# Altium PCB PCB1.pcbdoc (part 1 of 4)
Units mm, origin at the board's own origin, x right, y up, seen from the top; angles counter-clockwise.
Board outline 94.87 x 122.94 mm, 4 copper layers (Top Layer, Inner1, Inner2, Bottom Layer); 129 components, 127 nets, 713 pads, 345 vias.
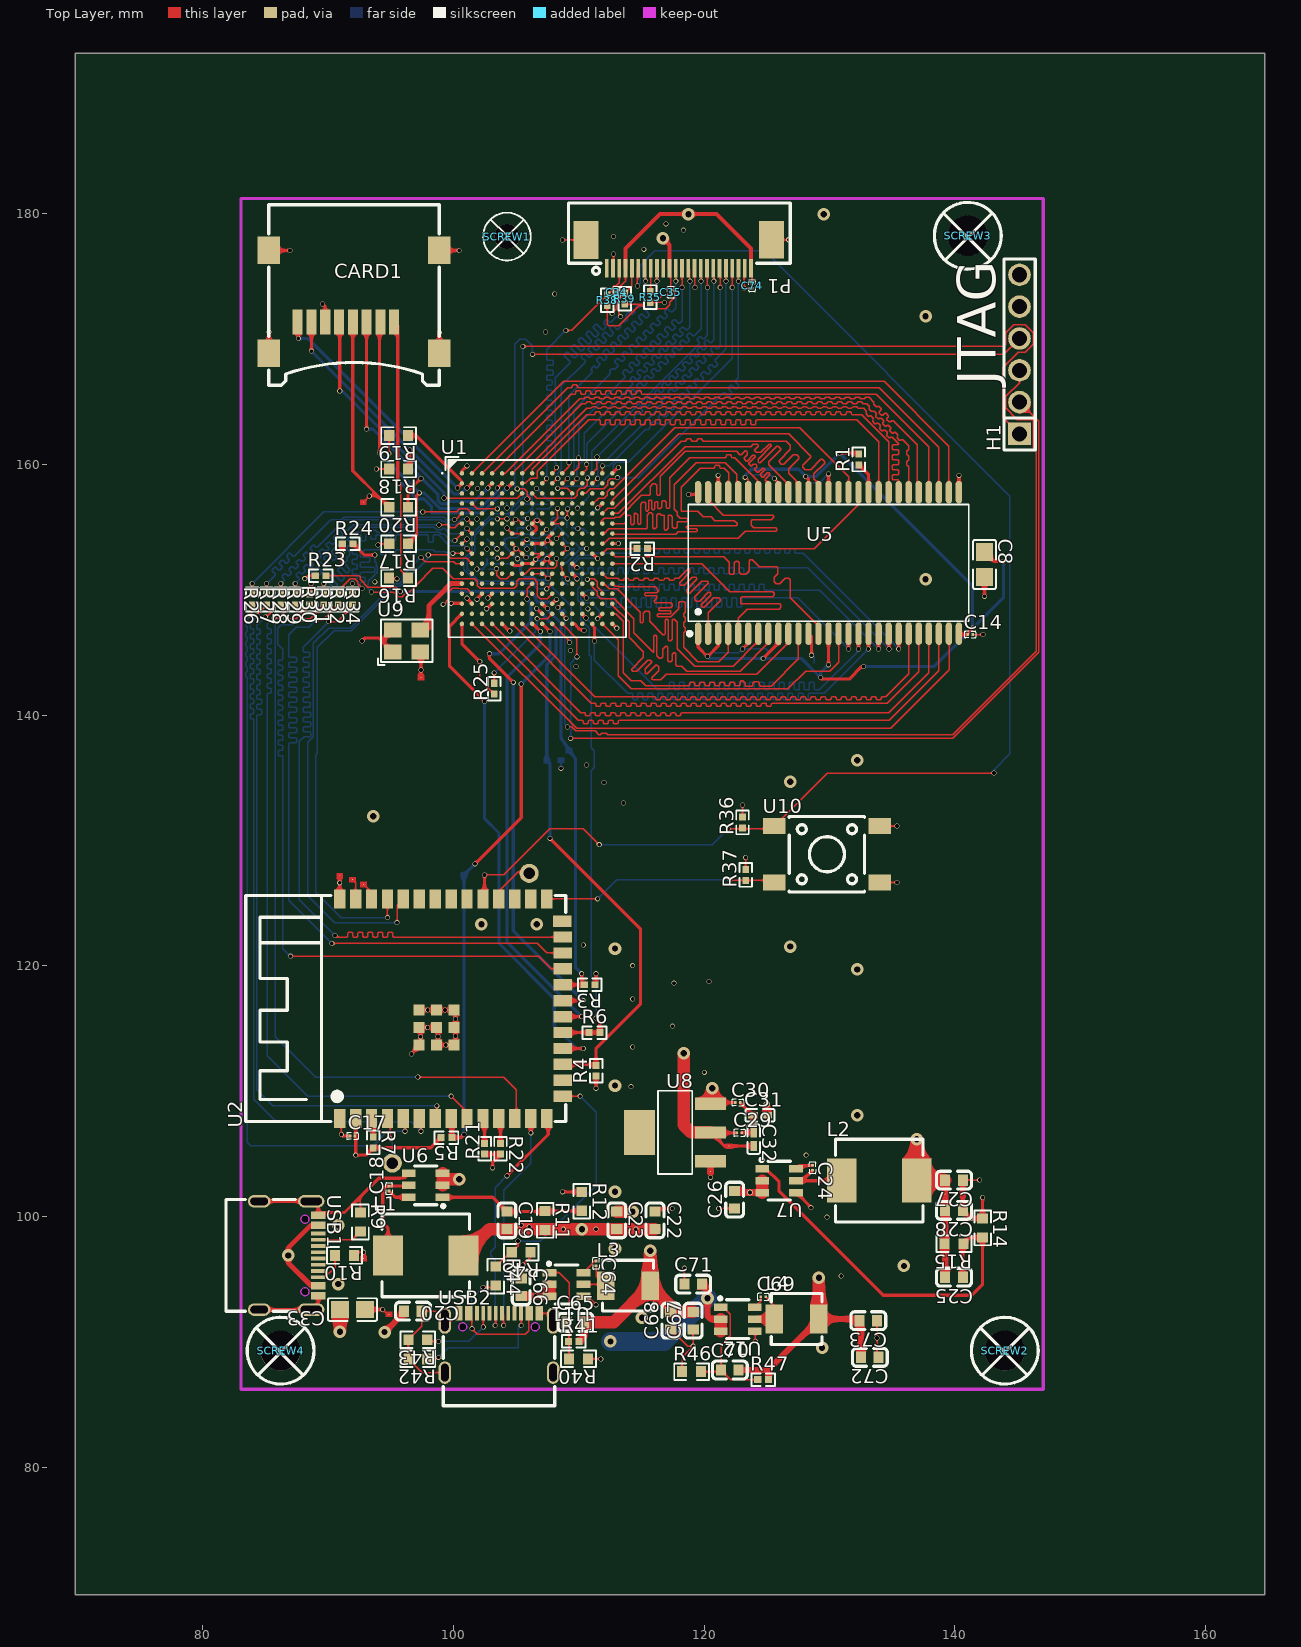
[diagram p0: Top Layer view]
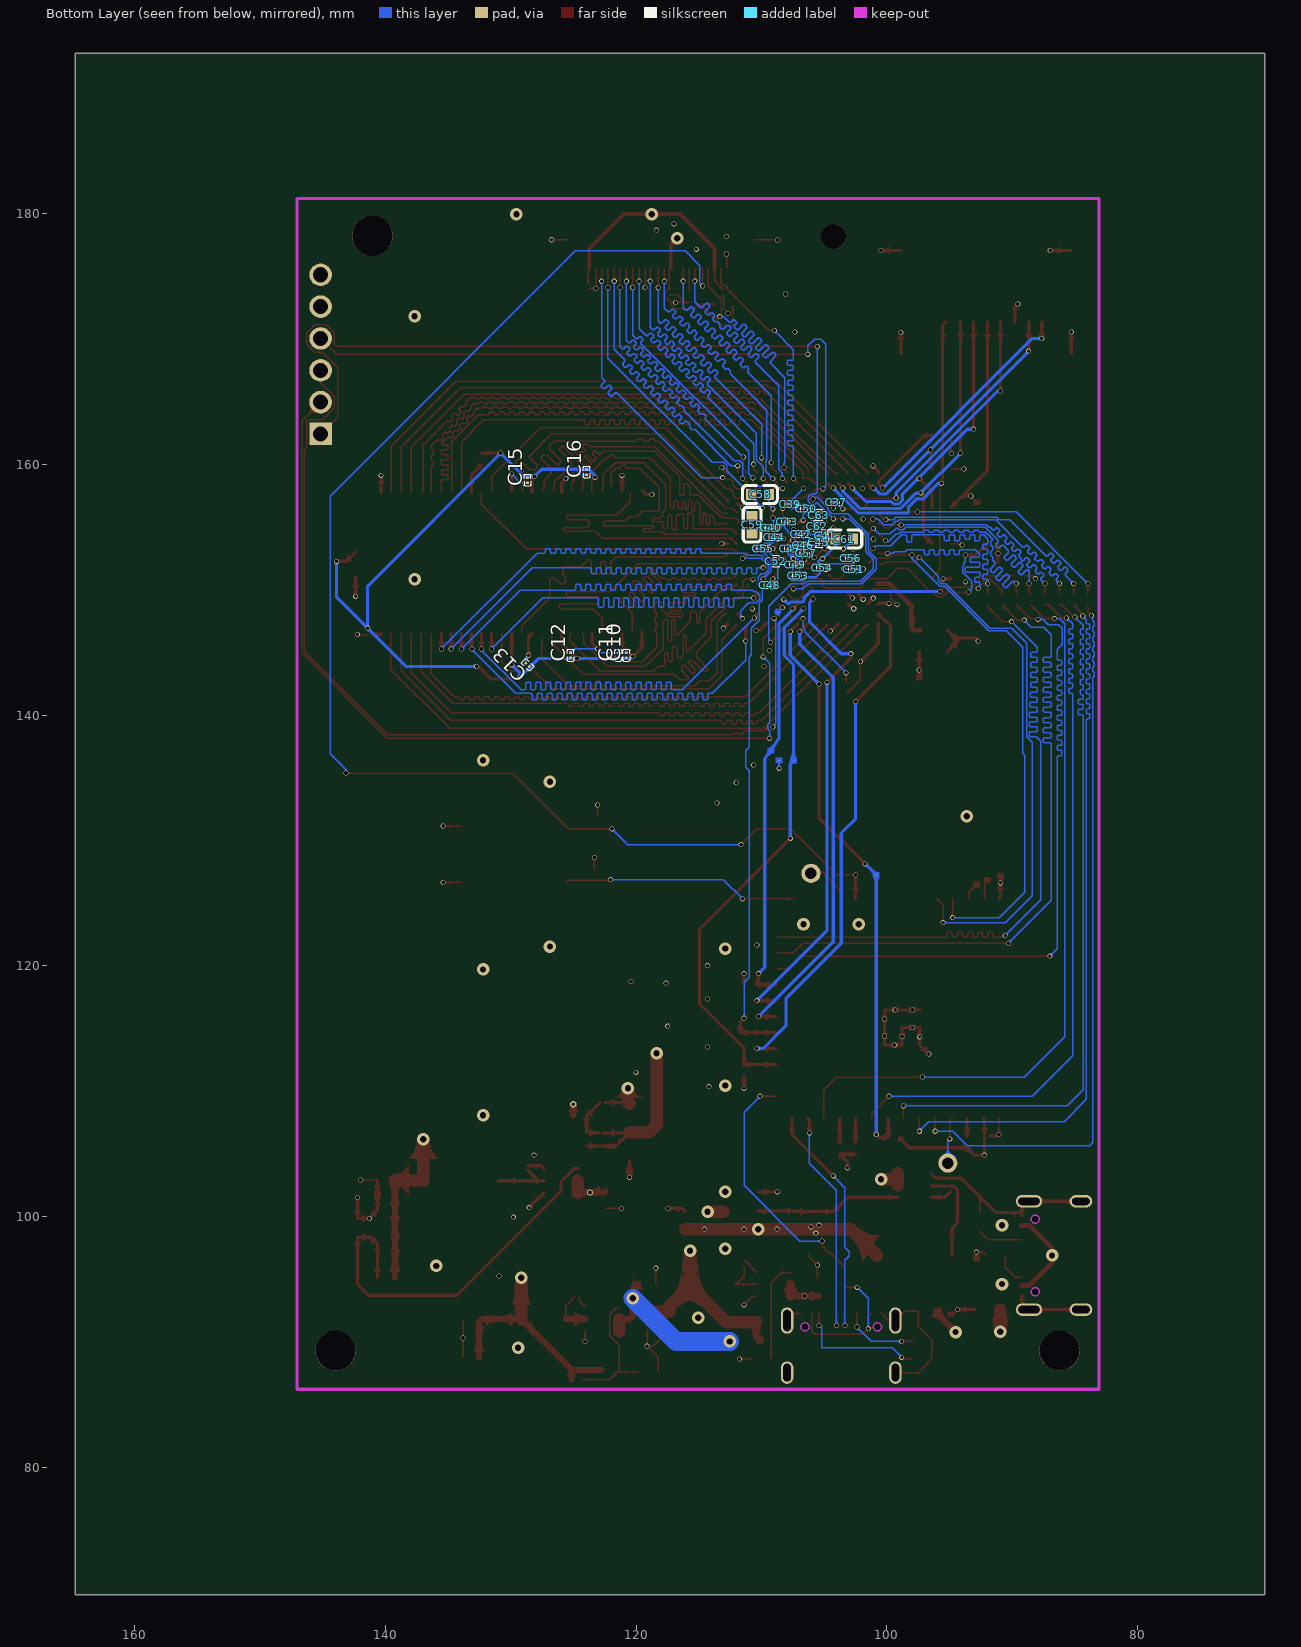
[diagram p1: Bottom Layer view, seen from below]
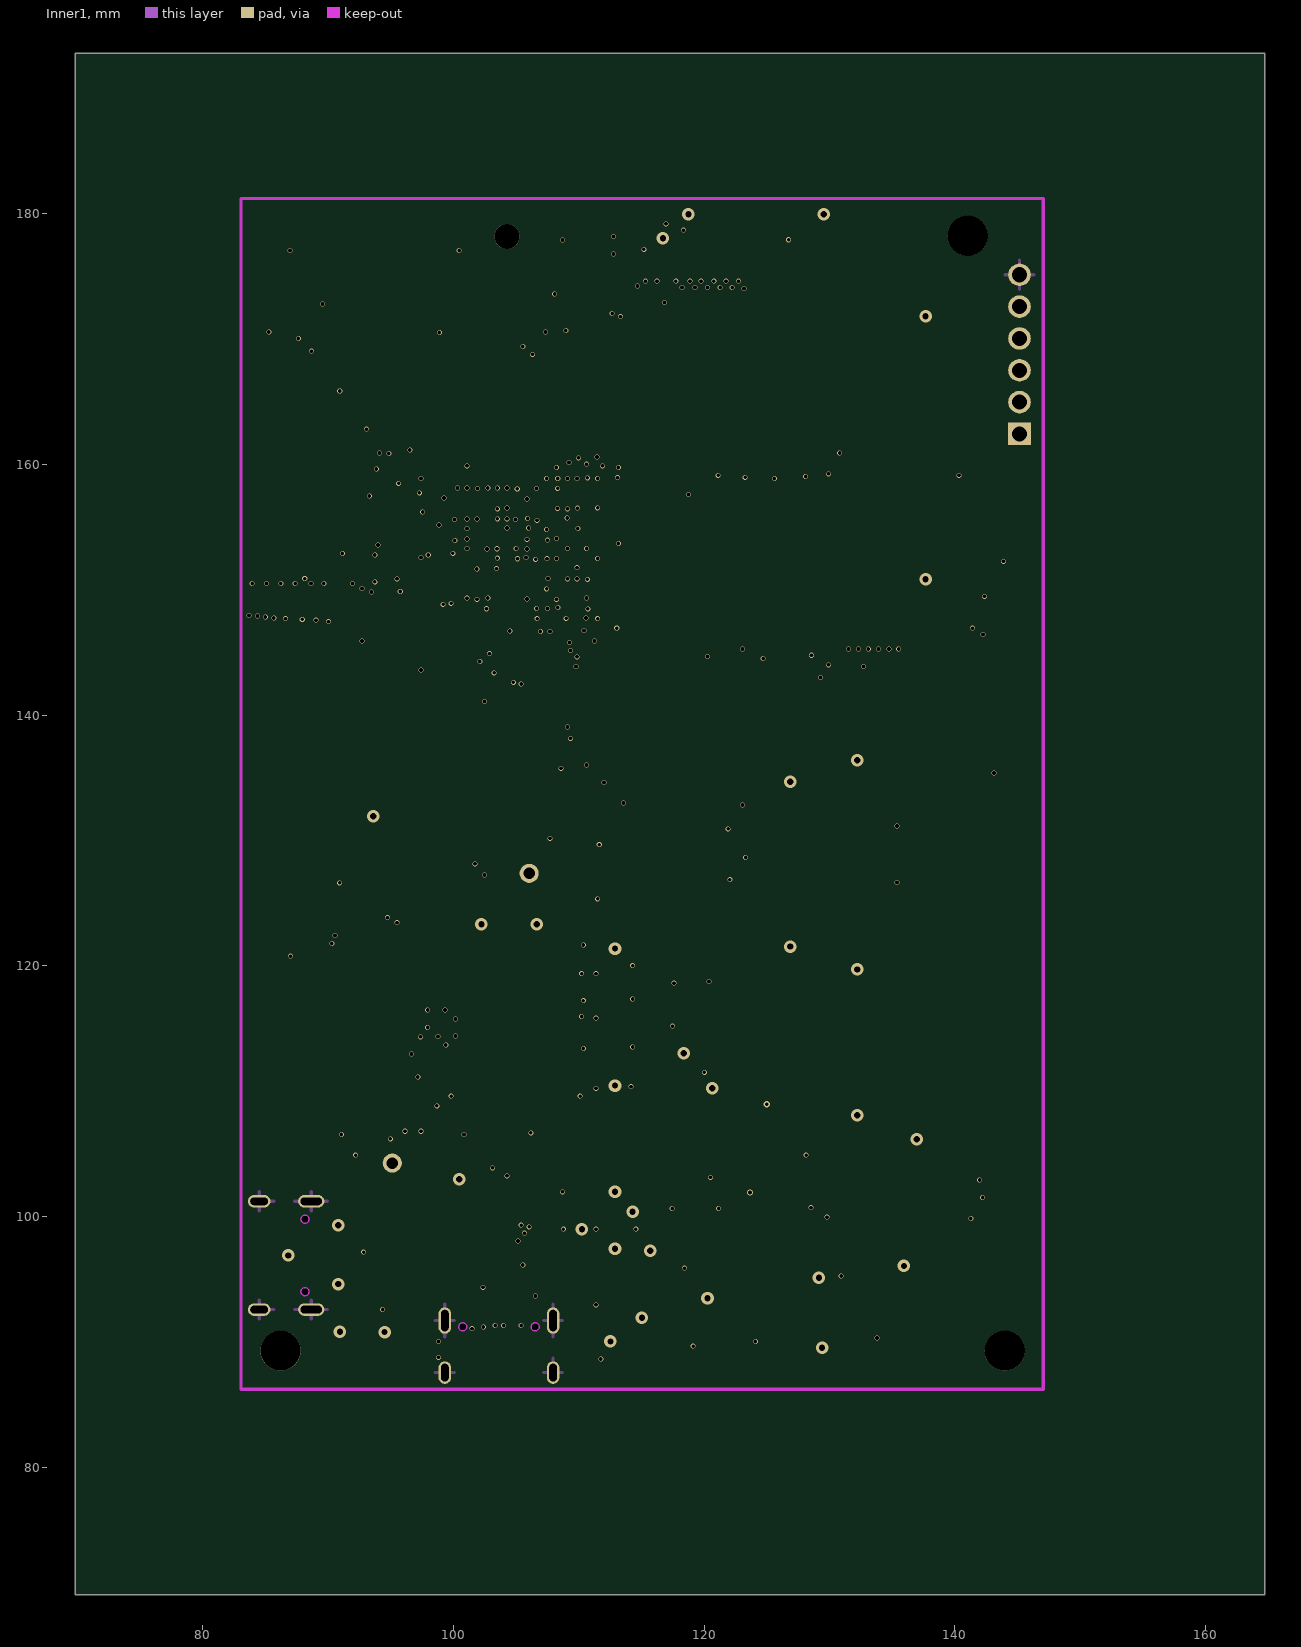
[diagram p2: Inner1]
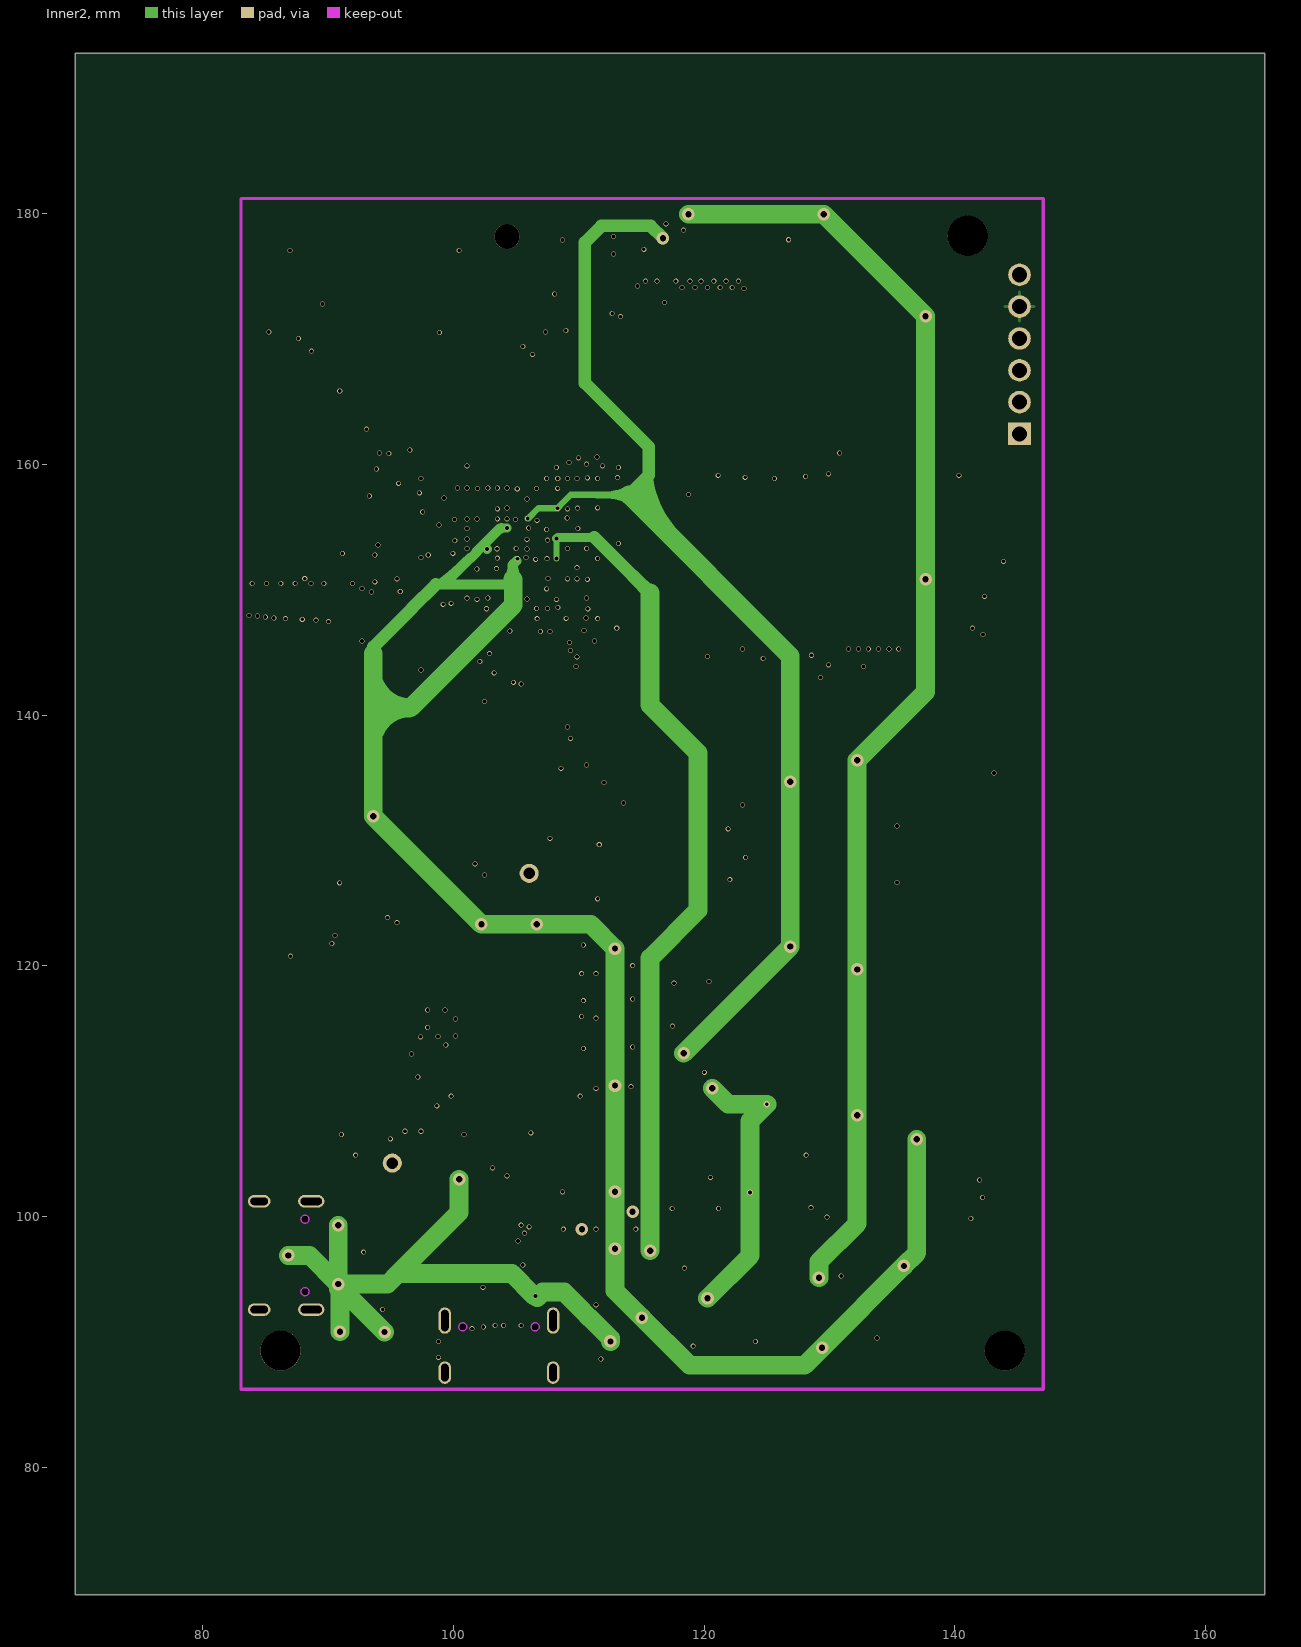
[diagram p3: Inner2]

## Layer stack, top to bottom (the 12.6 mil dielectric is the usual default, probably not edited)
Top Layer: signal copper (thickness not stored)
Dielectric: dielectric 0.32, FR-4, Dk 4.8
Inner1: signal copper (thickness not stored)
Dielectric: dielectric 0.32, FR-4, Dk 4.8
Inner2: signal copper (thickness not stored)
Dielectric: dielectric 0.32, FR-4, Dk 4.8
Bottom Layer: signal copper (thickness not stored)

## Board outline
164.719,69.85 69.85,69.85 69.85,192.786 164.719,192.786

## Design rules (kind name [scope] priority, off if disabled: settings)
BoardOutlineClearance copperThickness1oz [All] p0: genericclearance=0.254 ignorepadtopadclearanceinfootprint=FALSE except(0: Arc-SplitContinuation Track-SplitContinuation SMDPad-SplitContinuation THPad-SplitContinuation Via-SplitContinuation Fill-SplitContinuation Poly-SplitContinuation Region-SplitContinuation Text-SplitContinuation; 0.152: Track-CutoutEdge SMDPad-CutoutEdge THPad-CutoutEdge Via-CutoutEdge Region-CutoutEdge; 0.3: Track-OutlineEdge SMDPad-OutlineEdge THPad-OutlineEdge Via-OutlineEdge Fill-OutlineEdge Region-OutlineEdge Poly-OutlineEdge Text-OutlineEdge Fill-CutoutEdge)
BoardOutlineClearance copperThickness2oz [All] p0: genericclearance=0.254 ignorepadtopadclearanceinfootprint=FALSE except(0: Arc-SplitContinuation Track-SplitContinuation SMDPad-SplitContinuation THPad-SplitContinuation Via-SplitContinuation Fill-SplitContinuation Poly-SplitContinuation Region-SplitContinuation Text-SplitContinuation; 0.152: Track-CutoutEdge SMDPad-CutoutEdge THPad-CutoutEdge Via-CutoutEdge Region-CutoutEdge; 0.3: Track-OutlineEdge SMDPad-OutlineEdge THPad-OutlineEdge Via-OutlineEdge Fill-OutlineEdge Region-OutlineEdge Poly-OutlineEdge Text-OutlineEdge Fill-CutoutEdge)
Clearance copperThickness1oz [(InNet('SD_A0') OR InNet('SD_A1') OR InNet('SD_A2') OR InNet('SD_A3') OR InNet('SD_A4') OR InNet('SD_A5') OR InNet('SD_A6') OR InNet('SD_A7') OR InNet('SD_A8') OR InNet('SD_A9') OR InNet('SD_A10') OR InNet('SD_A11') OR InNet('SD_A12') OR InNet('SD_DQ15') OR InNet('SD_DQ14') OR InNet('SD_DQ8') OR InNet('SD_BA0') OR InNet('SD_BA1') OR InNet('SD_DQ9') OR InNet('SD_DQ7') OR InNet('SD_CLK') OR InNet('SD_WE_N') OR InNet('SD_DQ10') OR InNet('SD_CAS_N') OR InNet('SD_DQM1') OR InNet('SD_DQ2') OR InNet('SD_DQ3') OR InNet('SD_DQ11') OR InNet('SD_DQ12') OR InNet('SD_DQ13') OR InNet('SD_DQ0') OR InNet('SD_DQ1') OR InNet('SD_CS_N') OR InNet('SD_RAS_N') OR InNet('SD_DQ4') OR InNet('SD_DQ6') OR InNet('GND') OR InNet('SD_DQ5') OR InNet('SD_DQM0') OR InNet('$1N9437') OR InNet('+3V3') OR InNet('$1N11348') OR InNet('DOUT') OR InNet('DIN') OR InNet('CCLK') OR InNet('DONE') OR InNet('PROGRAMN') OR InNet('INITN') OR InNet('$1N11975') OR InNet('DN') OR InNet('DP') OR InNet('$1N14459') OR InNet('$1N14416') OR InNet('$1N14567') OR InNet('+5V') OR InNet('$1N16833') OR InNet('$1N16832') OR InNet('+1V1') OR InNet('$1N16834') OR InNet('+1V8') OR InNet('$1N17349') OR InNet('$1N12557') OR InNet('$1N12553') OR InNet('M_D2') OR InNet('M_D3') OR InNet('M_CMD') OR InNet('M_CLK') OR InNet('M_D0') OR InNet('M_D1') OR InNet('SDA') OR InNet('SCL') OR InNet('RESET') OR InNet('VSYNC') OR InNet('HREF') OR InNet('Y9') OR InNet('MCLK') OR InNet('Y8') OR InNet('Y7') OR InNet('PCLK') OR InNet('Y6') OR InNet('Y2') OR InNet('Y5') OR InNet('Y3') OR InNet('Y4') OR InNet('CRYSTAL') OR InNet('SSPI_CS_N') OR InNet('D0') OR InNet('D1') OR InNet('D2') OR InNet('D4') OR InNet('D3') OR InNet('D5') OR InNet('D6') OR InNet('D7') OR InNet('RX') OR InNet('TX') OR InNet('$1N29790') OR InNet('$1N29833') OR InNet('$1N29916') OR InNet('$1N29959') OR InNet('$1N30002') OR InNet('$1N30085') OR InNet('$1N30089') OR InNet('$1N30093') OR InNet('TDO') OR InNet('TDI') OR InNet('TMS') OR InNet('TCK') OR InNet('$1N33205') OR InNet('PROGRAM') OR InNet('$2N5507') OR InNet('$2N5509') OR InNet('$2N5511') OR InNet('FSDA') OR InNet('FSCL') OR InNet('+2V5') OR InNet('$1N60668') OR InNet('$1N60669') OR InNet('$1N60670') OR InNet('USB_VBUS') OR InNet('$1N63772') OR InNet('$1N63749') OR InNet('$1N63825') OR InNet('+2V8') OR InNet('$1N64402') OR InNet('$1N64401') OR InNet('$1N64403'))] p1: gap=0.178 ignorepadtopadclearanceinfootprint=FALSE except(0.099: Track-Track; 0.152: Track-SMDPad SMDPad-SMDPad Track-THPad SMDPad-THPad THPad-THPad Track-Via SMDPad-Via THPad-Via Via-Via SMDPad-Fill THPad-Fill Via-Fill Fill-Fill Track-Region SMDPad-Region THPad-Region Via-Region Region-Region Track-Poly SMDPad-Poly THPad-Poly Via-Poly Fill-Poly Region-Poly Poly-Poly Track-Text SMDPad-Text THPad-Text Via-Text Fill-Text Region-Text Poly-Text Text-Text; 0.175: Track-Hole SMDPad-Hole THPad-Hole Via-Hole Fill-Hole Region-Hole Poly-Hole Text-Hole Sheet-Hole; 0.3: Track-Fill Fill-Region Track-Sheet SMDPad-Sheet THPad-Sheet Via-Sheet Fill-Sheet Region-Sheet Poly-Sheet Text-Sheet)
Clearance copperThickness2oz [All] p1: gap=0.178 ignorepadtopadclearanceinfootprint=FALSE except(0.152: Track-SMDPad SMDPad-SMDPad Track-THPad SMDPad-THPad THPad-THPad Track-Via SMDPad-Via THPad-Via Via-Via SMDPad-Fill THPad-Fill Via-Fill Fill-Fill Track-Region SMDPad-Region THPad-Region Via-Region Region-Region Track-Poly SMDPad-Poly THPad-Poly Via-Poly Fill-Poly Region-Poly Poly-Poly Track-Text SMDPad-Text THPad-Text Via-Text Fill-Text Region-Text Poly-Text Text-Text; 0.175: Track-Hole SMDPad-Hole THPad-Hole Via-Hole Fill-Hole Region-Hole Poly-Hole Text-Hole Sheet-Hole; 0.203: Track-Track; 0.3: Track-Fill Fill-Region Track-Sheet SMDPad-Sheet THPad-Sheet Via-Sheet Fill-Sheet Region-Sheet Poly-Sheet Text-Sheet)
DiffPairsRouting differentialPair [All] p1: maxuncoupledlength=10 minlimit=6 maxlimit=6 mostfreqgap=6 toplayer_minwidth=5 toplayer_prefwidth=10 toplayer_maxwidth=100 bottomlayer_minwidth=5 bottomlayer_prefwidth=10 bottomlayer_maxwidth=100 midlayer1_minwidth=5 midlayer1_prefwidth=10 midlayer1_maxwidth=100 midlayer2_minwidth=5 midlayer2_prefwidth=10 midlayer2_maxwidth=100
PasteMaskExpansion pasteMaskExpansion [All] p1: expansion=0
PlaneConnect innerPlane [All] p1: planeconnectstyle=Relief reliefexpansion=0.508 reliefentries=4 reliefconductorwidth=0.254 reliefairgap=0.254
PolygonConnect copperRegion [All] p1: connectstyle=Relief reliefentries=4 reliefconductorwidth=10 polygonreliefangle="90 Angle" airgapwidth=10
RoutingVias viaSize [All] p1: viastyle="Through Hole" holewidth=11.811 minholewidth=11.811 maxholewidth=248.0314 width=15.748 minwidth=15.748 maxwidth=393.7008
SolderMaskExpansion solderMaskExpansion [All] p1: useseparateexpansions=TRUE expansion=2 expansionbottom=2
Width copperThickness1oz [All] p1: maxlimit=100 minlimit=4 preferedwidth=4
Width copperThickness2oz [All] p1: maxlimit=100 minlimit=8 preferedwidth=10

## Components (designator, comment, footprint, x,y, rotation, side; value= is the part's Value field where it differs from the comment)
C8 "CL21A476MQYNNNE" C0805 142.367,152.019 r270 top
C10 "GRM022R60J104KE15D" C01005 120.777,144.78 r90 bottom
C11 "GRM022R60J104KE15D" C01005 121.412,144.78 r90 bottom
C12 "GRM022R60J104KE15D" C01005 125.222,144.78 r90 bottom
C13 "GRM022R60J104KE15D" C01005 128.651,144.018 r45 bottom
C14 "GRM022R60J104KE15D" C01005 141.224,146.431 r0 top
C15 "GRM022R60J104KE15D" C01005 128.651,158.75 r90 bottom
C16 "GRM022R60J104KE15D" C01005 123.952,159.385 r90 bottom
C17 "GRM022R60J104KE15D" C01005 91.948,106.426 r0 top
C18 "GRM022R60J104KE15D" C01005 94.869,102.235 r90 top
C19 "TCC0603X7R104K500CT" C0603 104.267,99.695 r270 top
C20 "TCC0603X5R226M6R3CT" C0603 96.774,92.456 r180 top
C22 "TCC0603X5R226M6R3CT" C0603 116.078,99.695 r270 top
C23 "TCC0603X5R226M6R3CT" C0603 113.03,99.695 r270 top
C24 "GRM022R60J104KE15D" C01005 128.651,103.886 r270 top
C25 "TCC0603X7R104K500CT" C0603 139.933,95.162 r180 top
C26 "TCC0603X5R226M6R3CT" C0603 122.428,101.346 r90 top
C27 "TCC0603X5R226M6R3CT" C0603 139.933,102.909 r180 top
C28 "TCC0603X5R226M6R3CT" C0603 139.933,100.496 r180 top
C29 "GRM022R60J104KE15D" C01005 122.809,106.68 r0 top
C30 "GRM022R60J104KE15D" C01005 122.682,109.093 r0 top
C31 "GRM155R60J106ME44D" C0402 124.46,108.077 r0 top
C32 "GRM155R60J106ME44D" C0402 123.952,106.172 r270 top
C33 "CL21A476MQYNNNE" C0805 91.948,92.583 r180 top
C34 "GRM022R60J104KE15D" C01005 113.03,173.736 r270 top
C35 "GRM022R60J104KE15D" C01005 117.348,173.736 r270 top
C37 "GRM022R60J104KE15D" C01005 104.013,156.972 r180 bottom
C39 "GRM022R60J104KE15D" C01005 107.696,156.845 r180 bottom
C40 "GRM022R60J104KE15D" C01005 109.22,154.94 r180 bottom
C41 "GRM022R60J104KE15D" C01005 104.902,154.305 r90 bottom
C42 "GRM022R60J104KE15D" C01005 106.807,154.432 r180 bottom
C43 "GRM022R60J104KE15D" C01005 107.95,155.448 r180 bottom
C44 "GRM022R60J104KE15D" C01005 108.966,154.178 r180 bottom
C45 "GRM022R60J104KE15D" C01005 105.41,153.797 r270 bottom
C46 "GRM022R60J104KE15D" C01005 106.68,153.543 r180 bottom
C47 "GRM022R60J104KE15D" C01005 107.696,153.289 r0 bottom
C48 "GRM022R60J104KE15D" C01005 109.347,150.368 r180 bottom
C49 "GRM022R60J104KE15D" C01005 107.315,152.019 r180 bottom
C50 "GRM022R60J104KE15D" C01005 106.426,156.464 r180 bottom
C51 "GRM022R60J104KE15D" C01005 102.616,151.638 r180 bottom
C52 "GRM022R60J104KE15D" C01005 108.839,152.273 r270 bottom
C53 "GRM022R60J104KE15D" C01005 107.061,151.13 r180 bottom
C54 "GRM022R60J104KE15D" C01005 105.156,151.765 r180 bottom
C55 "GRM022R60J104KE15D" C01005 109.855,153.289 r0 bottom
C56 "GRM022R60J104KE15D" C01005 102.87,152.527 r180 bottom
C57 "GRM022R60J104KE15D" C01005 106.426,152.908 r0 bottom
C58 "TCC0603X5R226M6R3CT" C0603 110.109,157.607 r180 bottom
C59 "TCC0603X5R226M6R3CT" C0603 110.744,155.194 r90 bottom
C61 "TCC0603X5R226M6R3CT" C0603 103.378,154.051 r180 bottom
C62 "GRM022R60J104KE15D" C01005 105.537,155.067 r270 bottom
C63 "GRM022R60J104KE15D" C01005 105.41,155.956 r90 bottom
C64 "GRM022R60J104KE15D" C01005 111.379,96.266 r270 top
C65 "TCC0603X7R104K500CT" C0603 109.728,91.567 r0 top
C66 "TCC0603X5R226M6R3CT" C0603 105.41,94.361 r270 top
C67 "TCC0603X5R226M6R3CT" C0603 119.126,91.694 r90 top
C68 "TCC0603X5R226M6R3CT" C0603 117.348,91.694 r90 top
C69 "GRM022R60J104KE15D" C01005 124.714,93.599 r0 top
C70 "TCC0603X7R104K500CT" C0603 122.047,87.757 r0 top
C71 "TCC0603X5R226M6R3CT" C0603 119.126,94.615 r0 top
C72 "TCC0603X5R226M6R3CT" C0603 133.223,88.773 r180 top
C73 "TCC0603X5R226M6R3CT" C0603 133.096,91.694 r180 top
C74 "GRM022R60J104KE15D" C01005 123.825,174.244 r270 top
CARD1 "DS1139-06-08SS4BSR" TF-SMD_DS1139-06-08SS4BSR 92.075,172.974 r0 top
H1 "2.54-1x6P直针" HDR-TH_6P-P2.54-V-M-1 145.161,168.783 r90 top
L1 "FXL0630-6R8-M" IND-SMD_L7.0-W6.6 97.79,96.901 r0 top
L2 "FXL0630-100-M" IND-SMD_L7.3-W6.8 133.969,102.864 r0 top
L3 "SL0420-3R3M" IND-SMD_L4.5-W4.1_SL0420 113.919,94.488 r0 top
L4 "SL0420-3R3M" IND-SMD_L4.5-W4.1_SL0420 127.381,91.821 r0 top
P1 "AFC07-S24FCC-00" FPC-SMD_AFC07-S24FCC-00 117.983,176.784 r180 top
R1 "0402WGF1002TCE" R0402 132.334,160.401 r90 top
R2 "0402WGF330JTCE" R0402 115.062,153.289 r180 top
R3 "0402WGF1002TCE" R0402 110.871,118.491 r180 top
R4 "0402WGF1002TCE" R0402 111.379,111.633 r90 top
R5 "0402WGF1002TCE" R0402 99.441,106.299 r180 top
R6 "0402WGF330JTCE" R0402 111.252,114.681 r0 top
R7 "0402WGF1002TCE" R0402 93.599,105.918 r270 top
R9 "0603WAF5101T5E" R0603 92.583,99.568 r270 top
R10 "0603WAF5101T5E" R0603 91.313,96.901 r180 top
R11 "FRC0603F1963TS" R0603 107.315,99.695 r270 top
R12 "FRC0603F6202TS" R0603 110.236,101.219 r270 top
R14 "FRC0603F6202TS" R0603 142.219,99.099 r270 top
R15 "0603WAF2322T5E" R0603 139.933,97.829 r180 top
R16 "FRC0603F6202TS" R0603 95.627,150.952 r180 top
R17 "FRC0603F6202TS" R0603 95.631,153.67 r180 top
R18 "FRC0603F6202TS" R0603 95.631,159.639 r180 top
R19 "FRC0603F6202TS" R0603 95.631,162.306 r180 top
R20 "FRC0603F6202TS" R0603 95.631,156.591 r180 top
R21 "0402WGF1002TCE" R0402 102.489,105.41 r270 top
R22 "0402WGF1002TCE" R0402 103.759,105.41 r270 top
R23 "0402WGF1002TCE" R0402 89.408,151.13 r0 top
R24 "0402WGF1002TCE" R0402 91.567,153.67 r0 top
R25 "0402WGF1002TCE" R0402 103.251,142.113 r90 top
R26 "0402WGF330JTCE" R0402 83.947,149.225 r270 top
R27 "0402WGF330JTCE" R0402 85.09,149.225 r270 top
R28 "0402WGF330JTCE" R0402 86.233,149.225 r270 top
R29 "0402WGF330JTCE" R0402 87.376,149.225 r270 top
R30 "0402WGF330JTCE" R0402 88.519,149.225 r270 top
R31 "0402WGF330JTCE" R0402 89.662,149.225 r270 top
R32 "0402WGF330JTCE" R0402 90.805,149.225 r270 top
R34 "0402WGF330JTCE" R0402 91.948,149.225 r270 top
R35 "0402WGF1002TCE" R0402 115.697,173.355 r270 top
R36 "0402WGF1002TCE" R0402 123.063,131.445 r90 top
R37 "0402WGF1002TCE" R0402 123.317,127.254 r90 top
R38 "0402WGF1002TCE" R0402 112.268,173.101 r270 top
R39 "0402WGF1002TCE" R0402 113.665,173.228 r270 top
R40 "FRC0603F6202TS" R0603 109.982,88.646 r180 top
R41 "RC0402FR-07130KL" R0402 109.601,90.043 r0 top
R42 "0603WAF5101T5E" R0603 97.155,88.646 r180 top
R43 "0603WAF5101T5E" R0603 97.155,90.17 r180 top
R44 "FRC0603F1963TS" R0603 103.378,95.25 r270 top
R45 "FRC0603F1963TS" R0603 105.41,97.155 r180 top
R46 "FRC0603F6202TS" R0603 118.999,87.63 r0 top
R47 "0402WGF1543TCE" R0402 124.714,86.995 r0 top
SCREW1 "Screw-Hole-M2" Screw-Hole-M2 104.267,178.181 r0 top
SCREW2 "Screw-Hole-M3" Screw-Hole-M3 144.045,89.239 r0 top
SCREW3 "Screw-Hole-M3" Screw-Hole-M3 141.097,178.181 r0 top
SCREW4 "Screw-Hole-M3" Screw-Hole-M3 86.275,89.239 r0 top
U1 "LFE5U-25F-6BG256C" CABGA-256_L14.0-W14.0-R16-C16-P0.80-TL 106.68,153.289 r0 top
U2 "ESP32-S3-WROOM-1-N16R2" WIRELM-SMD_ESP32-S3-WROOM-1 99.822,116.586 r90 top
U5 "W9825G6KH-6" TSOP-54_L22.2-W10.2-P0.80-LS11.8-BL 129.921,152.146 r0 top
U6 "AP63200WU-7" SOT-23-6_L2.9-W1.6-P0.95-LS2.8-BR 97.79,102.489 r0 top
U7 "AP63200WU-7" SOT-23-6_L2.9-W1.6-P0.95-LS2.8-BR 125.984,102.87 r180 top
U8 "AMS1117-1.8_C6185" SOT-223-4_L6.5-W3.5-P2.30-LS7.0-BR 117.682,106.709 r0 top
U9 "XOS32024000LT00351005" OSC-SMD_4P-L3.2-W2.5-BL 96.266,145.923 r0 top
U10 "TPS645-5NC60" SW-SMD_4P-L6.0-W6.0-P4.50-LS9.2 129.794,128.905 r0 top
U11 "AP63200WU-7" SOT-23-6_L2.9-W1.6-P0.95-LS2.8-BR 109.019,94.587 r180 top
U12 "AP63200WU-7" SOT-23-6_L2.9-W1.6-P0.95-LS2.8-BR 122.682,91.821 r180 top
USB1 "TYPE-C16PIN" USB-C-SMD_TYPE-C16PIN#1 86.868,96.901 r270 top
USB2 "TYPE-C16PIN" USB-C-SMD_TYPE-C16PIN#2 103.632,89.916 r0 top

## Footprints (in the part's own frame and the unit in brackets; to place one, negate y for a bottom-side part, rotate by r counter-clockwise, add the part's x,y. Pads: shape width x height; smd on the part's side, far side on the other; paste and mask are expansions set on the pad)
C0402 [mm]
  rect 0.79x0.54 smd: 1(-0.545,0) 2(0.545,0)
  silkscreen extent -1.17,-0.5 1.17,0.5
C0603 [mm]
  rect 0.8x0.9 smd: 1(-0.7,0) 2(0.7,0)
  silkscreen extent -1.39,-0.71 1.39,0.71
C0805 [mm]
  rect 1.41x1.35 smd: 1(-1,0) 2(1,0)
  silkscreen extent -1.96,-0.9 1.96,0.9
C01005 [mm]
  rect 0.21x0.22 smd: 1(-0.195,0) 2(0.195,0)
  silkscreen extent -0.46,-0.27 0.46,0.27
CABGA-256_L14.0-W14.0-R16-C16-P0.80-TL [mm]
  round 0.36 smd: A1(-6,6) A2(-5.2,6) A3(-4.4,6) A4(-3.6,6) A5(-2.8,6) A6(-2,6) A7(-1.2,6) A8(-0.4,6) A9(0.4,6) A10(1.2,6) A11(2,6) A12(2.8,6) A13(3.6,6) A14(4.4,6) A15(5.2,6) A16(6,6) B1(-6,5.2) B2(-5.2,5.2) B3(-4.4,5.2) B4(-3.6,5.2) B5(-2.8,5.2) B6(-2,5.2) B7(-1.2,5.2) B8(-0.4,5.2) B9(0.4,5.2) B10(1.2,5.2) B11(2,5.2) B12(2.8,5.2) B13(3.6,5.2) B14(4.4,5.2) B15(5.2,5.2) B16(6,5.2) C1(-6,4.4) C2(-5.2,4.4) C3(-4.4,4.4) C4(-3.6,4.4) C5(-2.8,4.4) C6(-2,4.4) C7(-1.2,4.4) C8(-0.4,4.4) C9(0.4,4.4) C10(1.2,4.4) C11(2,4.4) C12(2.8,4.4) C13(3.6,4.4) C14(4.4,4.4) C15(5.2,4.4) C16(6,4.4) D1(-6,3.6) D2(-5.2,3.6) D3(-4.4,3.6) D4(-3.6,3.6) D5(-2.8,3.6) D6(-2,3.6) D7(-1.2,3.6) D8(-0.4,3.6) D9(0.4,3.6) D10(1.2,3.6) D11(2,3.6) D12(2.8,3.6) D13(3.6,3.6) D14(4.4,3.6) D15(5.2,3.6) D16(6,3.6) E1(-6,2.8) E2(-5.2,2.8) E3(-4.4,2.8) E4(-3.6,2.8) E5(-2.8,2.8) E6(-2,2.8) E7(-1.2,2.8) E8(-0.4,2.8) E9(0.4,2.8) E10(1.2,2.8) E11(2,2.8) E12(2.8,2.8) E13(3.6,2.8) E14(4.4,2.8) E15(5.2,2.8) E16(6,2.8) F1(-6,2) F2(-5.2,2) F3(-4.4,2) F4(-3.6,2) F5(-2.8,2) F6(-2,2) F7(-1.2,2) F8(-0.4,2) F9(0.4,2) F10(1.2,2) F11(2,2) F12(2.8,2) F13(3.6,2) F14(4.4,2) F15(5.2,2) F16(6,2) G1(-6,1.2) G2(-5.2,1.2) G3(-4.4,1.2) G4(-3.6,1.2) G5(-2.8,1.2) G6(-2,1.2) G7(-1.2,1.2) G8(-0.4,1.2) G9(0.4,1.2) G10(1.2,1.2) G11(2,1.2) G12(2.8,1.2) G13(3.6,1.2) G14(4.4,1.2) G15(5.2,1.2) G16(6,1.2) H1(-6,0.4) H2(-5.2,0.4) H3(-4.4,0.4) H4(-3.6,0.4) H5(-2.8,0.4) H6(-2,0.4) H7(-1.2,0.4) H8(-0.4,0.4) H9(0.4,0.4) H10(1.2,0.4) H11(2,0.4) H12(2.8,0.4) H13(3.6,0.4) H14(4.4,0.4) H15(5.2,0.4) H16(6,0.4) J1(-6,-0.4) J2(-5.2,-0.4) J3(-4.4,-0.4) J4(-3.6,-0.4) J5(-2.8,-0.4) J6(-2,-0.4) J7(-1.2,-0.4) J8(-0.4,-0.4) J9(0.4,-0.4) J10(1.2,-0.4) J11(2,-0.4) J12(2.8,-0.4) J13(3.6,-0.4) J14(4.4,-0.4) J15(5.2,-0.4) J16(6,-0.4) K1(-6,-1.2) K2(-5.2,-1.2) K3(-4.4,-1.2) K4(-3.6,-1.2) K5(-2.8,-1.2) K6(-2,-1.2) K7(-1.2,-1.2) K8(-0.4,-1.2) K9(0.4,-1.2) K10(1.2,-1.2) K11(2,-1.2) K12(2.8,-1.2) K13(3.6,-1.2) K14(4.4,-1.2) K15(5.2,-1.2) K16(6,-1.2) L1(-6,-2) L2(-5.2,-2) L3(-4.4,-2) L4(-3.6,-2) L5(-2.8,-2) L6(-2,-2) L7(-1.2,-2) L8(-0.4,-2) L9(0.4,-2) L10(1.2,-2) L11(2,-2) L12(2.8,-2) L13(3.6,-2) L14(4.4,-2) L15(5.2,-2) L16(6,-2) M1(-6,-2.8) M2(-5.2,-2.8) M3(-4.4,-2.8) M4(-3.6,-2.8) M5(-2.8,-2.8) M6(-2,-2.8) M7(-1.2,-2.8) M8(-0.4,-2.8) M9(0.4,-2.8) M10(1.2,-2.8) M11(2,-2.8) M12(2.8,-2.8) M13(3.6,-2.8) M14(4.4,-2.8) M15(5.2,-2.8) M16(6,-2.8) N1(-6,-3.6) N2(-5.2,-3.6) N3(-4.4,-3.6) N4(-3.6,-3.6) N5(-2.8,-3.6) N6(-2,-3.6) N7(-1.2,-3.6) N8(-0.4,-3.6) N9(0.4,-3.6) N10(1.2,-3.6) N11(2,-3.6) N12(2.8,-3.6) N13(3.6,-3.6) N14(4.4,-3.6) N15(5.2,-3.6) N16(6,-3.6) P1(-6,-4.4) P2(-5.2,-4.4) P3(-4.4,-4.4) P4(-3.6,-4.4) P5(-2.8,-4.4) P6(-2,-4.4) P7(-1.2,-4.4) P8(-0.4,-4.4) P9(0.4,-4.4) P10(1.2,-4.4) P11(2,-4.4) P12(2.8,-4.4) P13(3.6,-4.4) P14(4.4,-4.4) P15(5.2,-4.4) P16(6,-4.4) R1(-6,-5.2) R2(-5.2,-5.2) R3(-4.4,-5.2) R4(-3.6,-5.2) R5(-2.8,-5.2) R6(-2,-5.2) R7(-1.2,-5.2) R8(-0.4,-5.2) R9(0.4,-5.2) R10(1.2,-5.2) R11(2,-5.2) R12(2.8,-5.2) R13(3.6,-5.2) R14(4.4,-5.2) R15(5.2,-5.2) R16(6,-5.2) T1(-6,-6) T2(-5.2,-6) T3(-4.4,-6) T4(-3.6,-6) T5(-2.8,-6) T6(-2,-6) T7(-1.2,-6) T8(-0.4,-6) T9(0.4,-6) T10(1.2,-6) T11(2,-6) T12(2.8,-6) T13(3.6,-6) T14(4.4,-6) T15(5.2,-6) T16(6,-6)
  silkscreen extent -7.63,-7.08 7.08,7.3
FPC-SMD_AFC07-S24FCC-00 [mm]
  rect 0.3x1.5 smd: 1(5.745,1.129) 2(5.245,1.129) 3(4.746,1.129) 4(4.245,1.129) 5(3.746,1.129) 6(3.245,1.129) 7(2.746,1.129) 8(2.245,1.129) 9(1.746,1.129) 10(1.245,1.129) 11(0.746,1.129) 12(0.245,1.129) 13(-0.254,1.129) 14(-0.755,1.129) 15(-1.251,1.13) 16(-1.754,1.13) 17(-2.254,1.128) 18(-2.754,1.129) 19(-3.254,1.129) 20(-3.756,1.132) 21(-4.256,1.132) 22(-4.756,1.132) 23(-5.256,1.132) 24(-5.756,1.132)
  rect 2x3 smd: 25(-7.401,-1.132) 26(7.401,-1.125)
  silkscreen extent -8.89,-4.07 8.8,1.61
HDR-TH_6P-P2.54-V-M-1 [mm]
  rect 1.8x1.8 hole 1.2: 1(-6.35,0)
  round 1.8 hole 1.2: 2(-3.81,0) 3(-1.27,0) 4(1.27,0) 5(3.81,0) 6(6.35,0)
  silkscreen extent -7.62,-1.25 7.62,1.25
IND-SMD_L4.5-W4.1_SL0420 [mm]
  rect 1.4x2.3 smd: 1(-1.775,0) 2(1.775,0)
  silkscreen extent -2.03,-2.03 2.03,2.03
IND-SMD_L7.0-W6.6 [mm]
  rect 2.4x3.2 smd: 1(-3,0) 2(3,0)
  silkscreen extent -3.5,-3.3 3.5,3.3
IND-SMD_L7.3-W6.8 [mm]
  rect 2.35x3.5 smd: 1(-3,0) 2(3,0)
  silkscreen extent -3.5,-3.3 3.5,3.3
OSC-SMD_4P-L3.2-W2.5-BL [mm]
  rect 1.4x1.2 smd: 1(-1.1,-0.875) 2(1.1,-0.875) 3(1.1,0.875) 4(-1.1,0.875)
  silkscreen extent -2.29,-1.9 2.07,1.72
R0402 [mm]
  rect 0.566x0.54 smd: 1(-0.433,0) 2(0.433,0)
  silkscreen extent -0.94,-0.5 0.94,0.5
R0603 [mm]
  rect 0.806x0.864 smd: 1(-0.753,0) 2(0.753,0)
  silkscreen extent -1.39,-0.66 1.39,0.66
Screw-Hole-M2 [mm]
  round 2 hole 2: 1(0,0)
  silkscreen extent -1.9,-1.9 1.9,1.9
Screw-Hole-M3 [mil]
  round 126 hole 126: 1(-2.5,2.5)
  silkscreen extent -107,-102 102,107
SOT-23-6_L2.9-W1.6-P0.95-LS2.8-BR [mm]
  rect 1.1x0.6 smd: 1(1.35,-0.95) 2(1.35,0) 3(1.35,0.95) 4(-1.35,0.95) 5(-1.35,0) 6(-1.35,-0.95)
  silkscreen extent -0.9,-1.78 1.52,1.55
SOT-223-4_L6.5-W3.5-P2.30-LS7.0-BR [mm]
  rect 2.47x0.98 smd: 1(2.835,-2.3) 2(2.835,0) 3(2.835,2.3)
  rect 2.47x3.6 smd: 4(-2.835,0)
  silkscreen extent -1.37,-3.33 1.37,3.33
SW-SMD_4P-L6.0-W6.0-P4.50-LS9.2 [mm]
  rect 1.8x1.3 smd: 1(-4.2,2.25) 2(4.2,2.25) 3(-4.2,-2.25) 4(4.2,-2.25)
  silkscreen extent -3,-3 3,3
TF-SMD_DS1139-06-08SS4BSR [mm]
  rect 0.8x2 smd: 1(3.2,-1.6) 2(2.1,-1.6) 3(1,-1.6) 4(-0.1,-1.6) 5(-1.2,-1.6) 6(-2.3,-1.6) 7(-3.4,-1.6) 8(-4.5,-1.6)
  rect 1.8x2.2 smd: 9(-6.8,4.1) 10(-6.8,-4.1) 11(6.8,-4.1) 12(6.8,4.1)
  silkscreen extent -6.8,-6.65 6.8,7.75
TSOP-54_L22.2-W10.2-P0.80-LS11.8-BL [mm]
  oval 0.5x1.8 smd: 1(-10.4,-5.642) 2(-9.6,-5.642) 3(-8.8,-5.642) 4(-8,-5.642) 5(-7.2,-5.642) 6(-6.4,-5.642) 7(-5.6,-5.642) 8(-4.8,-5.642) 9(-4,-5.642) 10(-3.2,-5.642) 11(-2.4,-5.642) 12(-1.6,-5.642) 13(-0.8,-5.642) 14(0,-5.642) 15(0.8,-5.642) 16(1.6,-5.642) 17(2.4,-5.642) 18(3.2,-5.642) 19(4,-5.642) 20(4.8,-5.642) 21(5.6,-5.642) 22(6.4,-5.642) 23(7.2,-5.642) 24(8,-5.642) 25(8.8,-5.642) 26(9.6,-5.642) 27(10.4,-5.642) 28(10.4,5.642) 29(9.6,5.642) 30(8.8,5.642) 31(8,5.642) 32(7.2,5.642) 33(6.4,5.642) 34(5.6,5.642) 35(4.8,5.642) 36(4,5.642) 37(3.2,5.642) 38(2.4,5.642) 39(1.6,5.642) 40(0.8,5.642) 41(0,5.642) 42(-0.8,5.642) 43(-1.6,5.642) 44(-2.4,5.642) 45(-3.2,5.642) 46(-4,5.642) 47(-4.8,5.642) 48(-5.6,5.642) 49(-6.4,5.642) 50(-7.2,5.642) 51(-8,5.642) 52(-8.8,5.642) 53(-9.6,5.642) 54(-10.4,5.642)
  silkscreen extent -11.23,-5.79 11.19,4.65
USB-C-SMD_TYPE-C16PIN#1 [mm]
  oval 1x2.1 hole 0.6 slot 1.7 at 90 deg: 1(-4.32,1.787) 2(4.32,1.787)
  oval 1x1.8 hole 0.6 slot 1.4 at 90 deg: 3(-4.32,-2.362) 4(4.32,-2.362)
  rect 0.6x1.15 smd: A1B12(-3.2,2.362) A4B9(-2.4,2.362) B1A12(3.2,2.362) B4A9(2.4,2.362)
  rect 0.3x1.15 smd: A5(-1.25,2.362) A6(-0.25,2.362) A7(0.25,2.362) A8(1.25,2.362) B5(1.75,2.362) B6(0.75,2.362) B7(-0.75,2.362) B8(-1.75,2.362)
  Board Outline Layer circle w0.005: c2.89,1.288 r0.325
  Board Outline Layer circle w0.005: c-2.89,1.288 r0.325
  Board Outline Layer region: 2.89,1.613 3.031,1.581 3.144,1.491 3.207,1.36 3.207,1.216 3.144,1.085 3.031,0.995 2.89,0.963 2.89,0.963 2.749,0.995 2.636,1.085 2.573,1.216 2.573,1.36 2.636,1.491 2.749,1.581 2.89,1.613
  Board Outline Layer region: -2.89,1.613 -2.749,1.581 -2.636,1.491 -2.573,1.36 -2.573,1.216 -2.636,1.085 -2.749,0.995 -2.89,0.963 -2.89,0.963 -3.031,0.995 -3.144,1.085 -3.207,1.216 -3.207,1.36 -3.144,1.491 -3.031,1.581 -2.89,1.613
  Multi-Layer board cut-out: 2.89,1.613 3.031,1.581 3.144,1.491 3.207,1.36 3.207,1.216 3.144,1.085 3.031,0.995 2.89,0.963 2.89,0.963 2.749,0.995 2.636,1.085 2.573,1.216 2.573,1.36 2.636,1.491 2.749,1.581 2.89,1.613
  Multi-Layer board cut-out: -2.89,1.613 -2.749,1.581 -2.636,1.491 -2.573,1.36 -2.573,1.216 -2.636,1.085 -2.749,0.995 -2.89,0.963 -2.89,0.963 -3.031,0.995 -3.144,1.085 -3.207,1.216 -3.207,1.36 -3.144,1.491 -3.031,1.581 -2.89,1.613
  silkscreen extent -4.45,-5 4.45,0.52
USB-C-SMD_TYPE-C16PIN#2 [mm]
  oval 1x2.1 hole 0.6 slot 1.7 at 90 deg: 1(-4.32,1.787) 2(4.32,1.787)
  oval 1x1.8 hole 0.6 slot 1.4 at 90 deg: 3(-4.32,-2.362) 4(4.32,-2.362)
  rect 0.6x1.15 smd: A1B12(-3.2,2.362) A4B9(-2.4,2.362) B1A12(3.2,2.362) B4A9(2.4,2.362)
  rect 0.3x1.15 smd: A5(-1.25,2.362) A6(-0.25,2.362) A7(0.25,2.362) A8(1.25,2.362) B5(1.75,2.362) B6(0.75,2.362) B7(-0.75,2.362) B8(-1.75,2.362)
  Board Outline Layer circle w0.005: c2.89,1.288 r0.325
  Board Outline Layer circle w0.005: c-2.89,1.288 r0.325
  Board Outline Layer region: 3.215,1.288 3.183,1.147 3.093,1.034 2.962,0.971 2.818,0.971 2.687,1.034 2.597,1.147 2.565,1.288 2.565,1.288 2.597,1.429 2.687,1.542 2.818,1.605 2.962,1.605 3.093,1.542 3.183,1.429 3.215,1.288
  Board Outline Layer region: -2.565,1.288 -2.597,1.147 -2.687,1.034 -2.818,0.971 -2.962,0.971 -3.093,1.034 -3.183,1.147 -3.215,1.288 -3.215,1.288 -3.183,1.429 -3.093,1.542 -2.962,1.605 -2.818,1.605 -2.687,1.542 -2.597,1.429 -2.565,1.288
  Multi-Layer board cut-out: 3.215,1.288 3.183,1.147 3.093,1.034 2.962,0.971 2.818,0.971 2.687,1.034 2.597,1.147 2.565,1.288 2.565,1.288 2.597,1.429 2.687,1.542 2.818,1.605 2.962,1.605 3.093,1.542 3.183,1.429 3.215,1.288
  Multi-Layer board cut-out: -2.565,1.288 -2.597,1.147 -2.687,1.034 -2.818,0.971 -2.962,0.971 -3.093,1.034 -3.183,1.147 -3.215,1.288 -3.215,1.288 -3.183,1.429 -3.093,1.542 -2.962,1.605 -2.818,1.605 -2.687,1.542 -2.597,1.429 -2.565,1.288
  silkscreen extent -4.45,-5 4.45,0.52
WIRELM-SMD_ESP32-S3-WROOM-1 [mm]
  rect 1.5x0.9 smd: 1(-8.75,8.895) 2(-8.75,7.625) 3(-8.75,6.355) 4(-8.75,5.085) 5(-8.75,3.815) 6(-8.75,2.545) 7(-8.75,1.275) 8(-8.75,0.005) 9(-8.75,-1.265) 10(-8.75,-2.535) 11(-8.75,-3.805) 12(-8.75,-5.075) 13(-8.75,-6.345) 14(-8.75,-7.615) 27(8.75,-7.615) 28(8.75,-6.345) 29(8.75,-5.075) 30(8.75,-3.805) 31(8.75,-2.535) 32(8.75,-1.265) 33(8.75,0.005) 34(8.75,1.275) 35(8.75,2.545) 36(8.75,3.815) 37(8.75,5.085) 38(8.75,6.355) 39(8.75,7.625) 40(8.75,8.895)
  rect 0.9x1.5 smd: 15(-6.985,-8.895) 16(-5.715,-8.895) 17(-4.445,-8.895) 18(-3.175,-8.895) 19(-1.905,-8.895) 20(-0.635,-8.895) 21(0.635,-8.895) 22(1.905,-8.895) 23(3.175,-8.895) 24(4.445,-8.895) 25(5.715,-8.895) 26(6.985,-8.865)
  rect 0.9x0.9 smd: 41(-2.9,-0.225) 41(-2.9,1.175) 41(-2.9,2.575) 41(-1.5,2.575) 41(-1.5,-0.225) 41(-1.5,1.175) 41(-0.1,2.575) 41(-0.1,1.175) 41(-0.1,-0.225)
  silkscreen extent -9,-9.14 9.02,16.39

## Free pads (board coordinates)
  round 1.524 hole 0.914: 1(95.123,104.267) 1(106.045,127.381)
  round 0.08 smd: 55(90.927,127.195) 55(91.948,126.873) 55(92.806,156.993) 55(92.837,96.647) 55(92.837,126.492) 55(94.869,92.202) 55(97.409,143.002) 55(120.517,103.597) 55(121.997,105.627) 55(139.233,101.796) 55(140.633,101.756)
  round 0.08 smd far side: 55(100.838,127.254) 55(107.442,136.377) 55(108.585,136.398) 55(108.712,148.209) 55(109.22,137.16)

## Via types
v1: diameter 0.4, hole 0.3, Top Layer to Bottom Layer, 308 vias
v2: diameter 1, hole 0.5, Top Layer to Bottom Layer, 35 vias
v3: diameter 0.5, hole 0.3, Top Layer to Bottom Layer, 2 vias

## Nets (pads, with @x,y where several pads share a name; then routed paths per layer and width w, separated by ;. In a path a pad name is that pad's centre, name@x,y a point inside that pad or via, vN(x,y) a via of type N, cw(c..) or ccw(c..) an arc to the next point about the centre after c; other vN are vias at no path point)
$1N9437: R1.1 U5.37 | length 2.5
  Top Layer w0.254: R1.1@132.334,159.968 133.121,159.181 U5.37@133.121,157.788
$1N11348: R2.1 U5.38 | length 19.3
  Top Layer w0.1: R2.1@115.495,153.289 128.778,153.289 132.334,156.845 132.334,157.775 U5.38@132.321,157.788
$1N11975: R7.1 U2.3 | length 1.5
  Top Layer w0.254: U2.3@93.594,107.836 93.599,107.831 R7.1@93.599,106.351
$1N12553: R10.2 USB1.B5 | length 2.6
  Top Layer w0.1: USB1.B5@89.23,95.151 89.741,95.151 90.56,95.97 R10.2@90.56,96.901
$1N12557: R9.2 USB1.A5 | length 3.6
  Top Layer w0.1: USB1.A5@89.23,98.151 91.919,98.151 R9.2@92.583,98.815
$1N14416: C18.2 L1.1 U6.5 | length 7.6
  Top Layer w0.254: L1.1@94.79,96.901 94.79,99.06 94.361,99.489 94.361,102.141 94.643,102.424 94.863,102.424 C18.2@94.869,102.43 96.381,102.43 U6.5@96.44,102.489
$1N14459: C18.1 U6.6 | length 1.8
  Top Layer w0.254: C18.1@94.869,102.04 95.37,101.539 U6.6@96.44,101.539
$1N14567: C19.1 R11.1 R12.2 U6.1 | length 11.6
  Top Layer w0.254: U6.1@99.14,101.539 103.123,101.539 C19.1@104.267,100.395 107.262,100.395 R11.1@107.315,100.448 110.219,100.448 R12.2@110.236,100.466
$1N16832: C24.2 L2.1 U7.5 | length 5.3
  Top Layer w0.254: C24.2@128.651,103.691 127.83,102.87 U7.5@127.334,102.87 127.34,102.864 L2.1@130.969,102.864
$1N16833: C24.1 U7.6 | length 1.4
  Top Layer w0.254: U7.6@127.334,103.82 127.589,104.075 128.645,104.075 C24.1@128.651,104.081
$1N16834: C25.1 R14.2 R15.1 U7.1 | length 30.7
  Top Layer w0.254: U7.1@124.634,103.82 124.929,103.82 125.984,102.765 125.984,102.025 134.283,93.726 141.351,93.726 142.219,94.594 R14.2@142.219,98.346 141.203,98.346 R15.1@140.687,97.829 140.633,97.776 C25.1@140.633,95.162
$1N17349: C29.2 C30.2 C31.1 C32.1 | length 3.8
  Top Layer w0.254: C30.2@122.877,109.093 123.952,108.018 C32.1@123.952,106.717 123.041,106.717 C29.2@123.004,106.68
$1N29790: R26.2 U2.5 | length 57.9
  Top Layer w0.1: v1(83.685,147.955) 83.947,148.217 R26.2@83.947,148.792 ; U2.5@96.134,107.836 96.139,107.831 v1(96.139,106.807)
  Bottom Layer w0.1: v1(83.685,147.955) 83.566,147.836 83.566,147.523 83.437,147.395 83.437,147.123 83.566,146.995 83.566,146.723 83.437,146.595 83.437,146.323 83.566,146.195 83.566,145.923 83.437,145.795 83.437,145.523 83.566,145.395 83.566,145.123 83.437,144.995 83.437,144.723 83.566,144.595 83.566,144.323 83.437,144.195 83.437,143.923 83.566,143.795 83.566,143.523 83.437,143.395 83.437,143.123 83.566,142.995 83.566,105.918 83.82,105.664 93.598,105.664 94.741,106.807 v1(96.139,106.807)
$1N29833: R27.2 U2.6 | length 59.2
  Top Layer w0.1: v1(84.364,147.919) 84.364,148.066 R27.2@85.09,148.792 ; v1(97.404,106.807) U2.6@97.404,107.836
  Bottom Layer w0.1: v1(84.364,147.919) 84.074,147.629 84.074,147.358 84.003,147.287 83.866,147.287 83.795,147.217 83.795,146.958 83.866,146.887 84.003,146.887 84.074,146.817 84.074,146.558 84.003,146.487 83.866,146.487 83.795,146.417 83.795,146.158 83.866,146.087 84.003,146.087 84.074,146.017 84.074,145.758 84.003,145.687 83.866,145.687 83.795,145.617 83.795,145.358 83.866,145.287 84.003,145.287 84.074,145.217 84.074,144.958 84.003,144.887 83.866,144.887 83.795,144.817 83.795,144.558 83.866,144.487 84.003,144.487 84.074,144.417 84.074,144.158 84.003,144.087 83.866,144.087 83.795,144.017 83.795,143.758 83.866,143.687 84.003,143.687 84.074,143.617 84.074,143.358 84.003,143.287 83.866,143.287 83.795,143.217 83.795,142.958 83.866,142.887 84.003,142.887 84.074,142.817 84.074,142.558 84.003,142.487 83.866,142.487 83.795,142.417 83.795,142.158 83.866,142.087 84.003,142.087 84.074,142.017 84.074,141.794 84.003,141.723 83.866,141.723 83.795,141.653 83.795,141.394 83.866,141.323 84.003,141.323 84.074,141.253 84.074,140.994 84.003,140.923 83.866,140.923 83.795,140.853 83.795,140.594 83.866,140.523 84.003,140.523 84.074,140.453 84.074,140.194 84.003,140.123 83.866,140.123 83.795,140.053 83.795,139.794 83.866,139.723 84.003,139.723 84.074,139.653 84.074,109.347 85.852,107.569 96.642,107.569 v1(97.404,106.807)
$1N29916: R29.2 U2.9 | length 59.1
  Top Layer w0.1: v1(85.675,147.751) 86.03,147.751 87.072,148.792 R29.2@87.376,148.792 ; v1(99.822,109.601) 101.214,108.209 U2.9@101.214,107.836
  Bottom Layer w0.1: v1(85.675,147.751) 85.473,147.549 85.417,147.549 85.144,147.276 85.144,146.979 85.215,146.909 85.4,146.909 85.471,146.838 85.471,146.579 85.4,146.509 85.215,146.509 85.144,146.438 85.144,146.179 85.215,146.109 85.4,146.109 85.471,146.038 85.471,145.779 85.4,145.709 85.215,145.709 85.144,145.638 85.144,145.379 85.215,145.309 85.4,145.309 85.471,145.238 85.471,144.979 85.4,144.909 85.215,144.909 85.144,144.838 85.144,144.579 85.215,144.509 85.4,144.509 85.471,144.438 85.471,144.179 85.4,144.109 85.215,144.109 85.144,144.038 85.144,143.779 85.215,143.709 85.4,143.709 85.471,143.638 85.471,143.379 85.4,143.309 85.215,143.309 85.144,143.238 85.144,143.024 85.215,142.954 85.4,142.954 85.471,142.883 85.471,142.624 85.4,142.554 85.215,142.554 85.144,142.483 85.144,142.224 85.215,142.154 85.4,142.154 85.471,142.083 85.471,141.824 85.4,141.754 85.215,141.754 85.144,141.683 85.144,112.849 88.392,109.601 v1(99.822,109.601)
$1N29959: R30.2 U2.12 | length 59.5
  Top Layer w0.1: v1(86.614,147.701) 87.428,147.701 R30.2@88.519,148.792 ; v1(97.155,111.125) 104.013,111.125 105.024,110.114 U2.12@105.024,107.836
  Bottom Layer w0.1: v1(86.614,147.701) 86.194,147.701 85.842,147.349 85.842,147.339 85.798,147.295 85.798,114.354 89.027,111.125 v1(97.155,111.125)
$1N30002: R31.2 U2.23 | length 58.9
  Top Layer w0.1: v1(86.995,120.777) 106.807,120.777 107.823,119.761 U2.23@108.717,119.761 ; v1@87.884,147.701 88.571,147.701 R31.2@89.662,148.792
  Bottom Layer w0.1: v1(86.995,120.777) 86.399,121.373 86.399,136.711 86.328,136.782 86.098,136.782 86.027,136.852 86.027,137.111 86.098,137.182 86.328,137.182 86.399,137.252 86.399,137.511 86.328,137.582 86.098,137.582 86.027,137.652 86.027,137.911 86.098,137.982 86.328,137.982 86.399,138.052 86.399,138.311 86.328,138.382 86.098,138.382 86.027,138.452 86.027,138.711 86.098,138.782 86.328,138.782 86.399,138.852 86.399,139.111 86.328,139.182 86.098,139.182 86.027,139.252 86.027,139.511 86.098,139.582 86.328,139.582 86.399,139.652 86.399,139.911 86.328,139.982 86.098,139.982 86.027,140.052 86.027,140.311 86.098,140.382 86.328,140.382 86.399,140.452 86.399,140.711 86.328,140.782 86.098,140.782 86.027,140.852 86.027,141.111 86.098,141.182 86.328,141.182 86.399,141.252 86.399,141.511 86.328,141.582 86.098,141.582 86.027,141.652 86.027,141.911 86.098,141.982 86.328,141.982 86.399,142.052 86.399,142.311 86.328,142.382 86.098,142.382 86.027,142.452 86.027,142.711 86.098,142.782 86.328,142.782 86.399,142.852 86.399,143.111 86.328,143.182 86.098,143.182 86.027,143.252 86.027,143.511 86.098,143.582 86.328,143.582 86.399,143.652 86.399,143.911 86.328,143.982 86.098,143.982 86.027,144.052 86.027,144.311 86.098,144.382 86.328,144.382 86.399,144.452 86.399,145.249 85.998,145.65 85.998,146.933 86.277,147.212 87.126,147.212 87.559,147.645 v1(87.94,147.645)
$1N30085: R34.2 U2.25 | length 59.4
  Top Layer w0.1: v1@90.043,147.447 90.73,147.447 91.948,148.665 R34.2@91.948,148.792 ; v1(90.551,122.428) 90.678,122.301 91.486,122.301 91.557,122.372 91.557,122.611 91.628,122.682 91.886,122.682 91.957,122.611 91.957,122.372 92.028,122.301 92.286,122.301 92.357,122.372 92.357,122.611 92.428,122.682 92.686,122.682 92.757,122.611 92.757,122.372 92.828,122.301 93.086,122.301 93.157,122.372 93.157,122.611 93.228,122.682 93.486,122.682 93.557,122.611 93.557,122.372 93.628,122.301 93.886,122.301 93.957,122.372 93.957,122.611 94.028,122.682 94.286,122.682 94.357,122.611 94.357,122.372 94.428,122.301 94.686,122.301 94.757,122.372 94.757,122.611 94.828,122.682 95.086,122.682 95.157,122.611 95.157,122.372 95.228,122.301 U2.25@108.717,122.301
  Bottom Layer w0.1: v1(90.036,147.454) 88.011,145.43 88.011,145.109 88.082,145.038 88.448,145.038 88.519,144.968 88.519,144.709 88.448,144.638 88.082,144.638 88.011,144.568 88.011,144.309 88.082,144.238 88.438,144.238 88.509,144.168 88.509,143.909 88.438,143.838 88.082,143.838 88.011,143.768 88.011,143.509 88.082,143.438 88.447,143.438 88.518,143.368 88.518,143.109 88.447,143.038 88.082,143.038 88.011,142.968 88.011,142.709 88.082,142.638 88.438,142.638 88.509,142.568 88.509,142.309 88.438,142.238 88.082,142.238 88.011,142.168 88.011,141.909 88.082,141.838 88.483,141.838 88.553,141.768 88.553,141.509 88.483,141.438 88.082,141.438 88.011,141.368 88.011,141.109 88.082,141.038 88.51,141.038 88.58,140.968 88.58,140.709 88.51,140.638 88.082,140.638 88.011,140.568 88.011,140.309 88.082,140.238 88.555,140.238 88.625,140.168 88.625,139.909 88.555,139.838 88.082,139.838 88.011,139.768 88.011,139.554 88.082,139.483 88.561,139.483 88.632,139.412 88.632,139.154 88.561,139.083 88.082,139.083 88.011,139.012 88.011,138.754 88.082,138.683 88.561,138.683 88.632,138.612 88.632,138.354 88.561,138.283 88.082,138.283 87.703,137.904 87.703,125.276 v1(90.551,122.428)
$1N30089: R32.2 U2.24 | length 59.6
  Top Layer w0.1: v1(89.027,147.574) 89.587,147.574 R32.2@90.805,148.792 ; v1(90.297,121.793) 106.68,121.793 107.442,121.031 U2.24@108.717,121.031
  Bottom Layer w0.1: v1(89.027,147.574) 88.465,147.012 87.464,147.012 86.868,146.416 86.868,144.684 86.939,144.614 87.432,144.614 87.503,144.543 87.503,144.284 87.432,144.214 86.939,144.214 86.868,144.143 86.868,143.884 86.939,143.814 87.432,143.814 87.503,143.743 87.503,143.484 87.432,143.414 86.939,143.414 86.868,143.343 86.868,143.084 86.939,143.014 87.432,143.014 87.503,142.943 87.503,142.684 87.432,142.614 86.939,142.614 86.868,142.543 86.868,142.284 86.939,142.214 87.432,142.214 87.503,142.143 87.503,141.884 87.432,141.814 86.939,141.814 86.868,141.743 86.868,141.484 86.939,141.414 87.432,141.414 87.503,141.343 87.503,141.084 87.432,141.014 86.939,141.014 86.868,140.943 86.868,140.684 86.939,140.614 87.432,140.614 87.503,140.543 87.503,140.284 87.432,140.214 86.939,140.214 86.868,140.143 86.868,139.884 86.939,139.814 87.432,139.814 87.503,139.743 87.503,139.484 87.432,139.414 86.939,139.414 86.868,139.343 86.868,139.084 86.939,139.014 87.432,139.014 87.503,138.943 87.503,138.684 87.432,138.614 86.939,138.614 86.868,138.543 86.868,138.284 86.939,138.214 87.432,138.214 87.503,138.143 87.503,137.884 87.432,137.814 86.939,137.814 86.868,137.743 86.868,125.222 v1(90.297,121.793)
$1N30093: R28.2 U2.7 | length 59.1
  Top Layer w0.1: v1(84.996,147.828) 85.057,147.828 86.022,148.792 R28.2@86.233,148.792 ; U2.7@98.674,107.836 v1(98.674,108.839)
  Bottom Layer w0.1: v1(84.996,147.828) 84.328,147.16 84.328,146.916 84.399,146.845 84.511,146.845 84.582,146.774 84.582,146.516 84.511,146.445 84.399,146.445 84.328,146.374 84.328,146.116 84.399,146.045 84.511,146.045 84.582,145.974 84.582,145.716 84.511,145.645 84.399,145.645 84.328,145.574 84.328,145.316 84.399,145.245 84.511,145.245 84.582,145.174 84.582,144.916 84.511,144.845 84.399,144.845 84.328,144.774 84.328,144.516 84.399,144.445 84.511,144.445 84.582,144.374 84.582,144.116 84.511,144.045 84.399,144.045 84.328,143.974 84.328,143.716 84.399,143.645 84.511,143.645 84.582,143.574 84.582,143.316 84.511,143.245 84.399,143.245 84.328,143.174 84.328,142.916 84.399,142.845 84.511,142.845 84.582,142.774 84.582,142.516 84.511,142.445 84.399,142.445 84.328,142.374 84.328,142.116 84.399,142.045 84.511,142.045 84.582,141.974 84.582,141.716 84.511,141.645 84.399,141.645 84.328,141.574 84.328,141.324 84.399,141.253 84.638,141.253 84.709,141.182 84.709,140.924 84.638,140.853 84.399,140.853 84.328,140.782 84.328,140.524 84.399,140.453 84.638,140.453 84.709,140.382 84.709,140.124 84.638,140.053 84.399,140.053 84.328,139.982 84.328,110.109 85.598,108.839 v1(98.674,108.839)
$1N33205: P1.8 R35.1 | length 1.9
  Top Layer w0.1: R35.1@115.697,173.788 115.738,173.828 P1.8@115.738,175.655
$1N60668: C64.1 U11.6 | length 1.4
  Top Layer w0.1: U11.6@110.369,95.537 111.067,96.235 111.067,96.26 111.185,96.378 111.21,96.378 111.293,96.461 C64.1@111.379,96.461
$1N60669: C64.2 L3.1 U11.5 | length 3.6
  Top Layer w0.1: U11.5@110.369,94.587 L3.1@112.045,94.587 ; C64.2@111.379,96.071 111.379,95.253 L3.1@112.045,94.587 ; L3.1@112.144,94.488 L3.1@112.045,94.587
$1N60670: C65.1 R40.2 R41.1 U11.1 | length 8
  Top Layer w0.1: U11.1@107.669,95.537 108.425,95.537 109.229,94.733 R40.2@109.229,88.646
$1N63749: R43.1 USB2.A5 | length 6.1
  Top Layer w0.1: R43.1@97.908,90.17 98.035,90.043 v1(98.806,90.043) ; v1(102.382,91.186) USB2.A5@102.382,92.278
  Bottom Layer w0.1: v1(98.806,90.043) 101.239,90.043 v1(102.382,91.186)
$1N63772: R42.1 USB2.B5 | length 10.5
  Top Layer w0.1: R42.1@97.908,88.646 98.679,88.646 v1(98.806,88.773) ; USB2.B5@105.382,92.278 105.41,92.251 v1(105.41,91.313)
  Bottom Layer w0.1: v1(98.806,88.773) 99.568,89.535 105.156,89.535 105.184,89.563 105.184,91.087 v1(105.41,91.313)
$1N63825: R44.2 USB2.A4B9 USB2.B4A9 | length 12.3
  Top Layer w0.1: USB2.A4B9@101.232,92.278 101.473,92.037 v1(101.473,91.059) 101.912,90.62 105.733,90.62 105.995,90.882 105.995,92.241 USB2.B4A9@106.032,92.278 ; v1(102.362,94.361) 103.242,94.361 R44.2@103.378,94.497
  Bottom Layer w0.1: v1(101.473,91.059) 101.473,93.472 v1(102.362,94.361)
$1N64401: C69.2 L4.1 U12.5 | length 3.6
  Top Layer w0.1: C69.2@124.909,93.599 125.606,92.902 L4.1@125.606,91.821
  Top Layer w0.5: U12.5@124.032,91.821 L4.1@125.606,91.821
$1N64402: C69.1 U12.6 | length 1
  Top Layer w0.1: U12.6@124.032,92.771 124.519,93.258 C69.1@124.519,93.599
$1N64403: C70.1 R46.2 R47.1 U12.1 | length 10.6
  Top Layer w0.1: R46.2@119.752,87.63 121.22,87.63 C70.1@121.347,87.757 ; U12.1@121.332,92.771 121.393,92.71 121.579,92.71 122.084,92.205 122.084,90.487 121.347,89.75 C70.1@121.347,87.757 ; R47.1@124.281,86.995 122.109,86.995 C70.1@121.347,87.757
